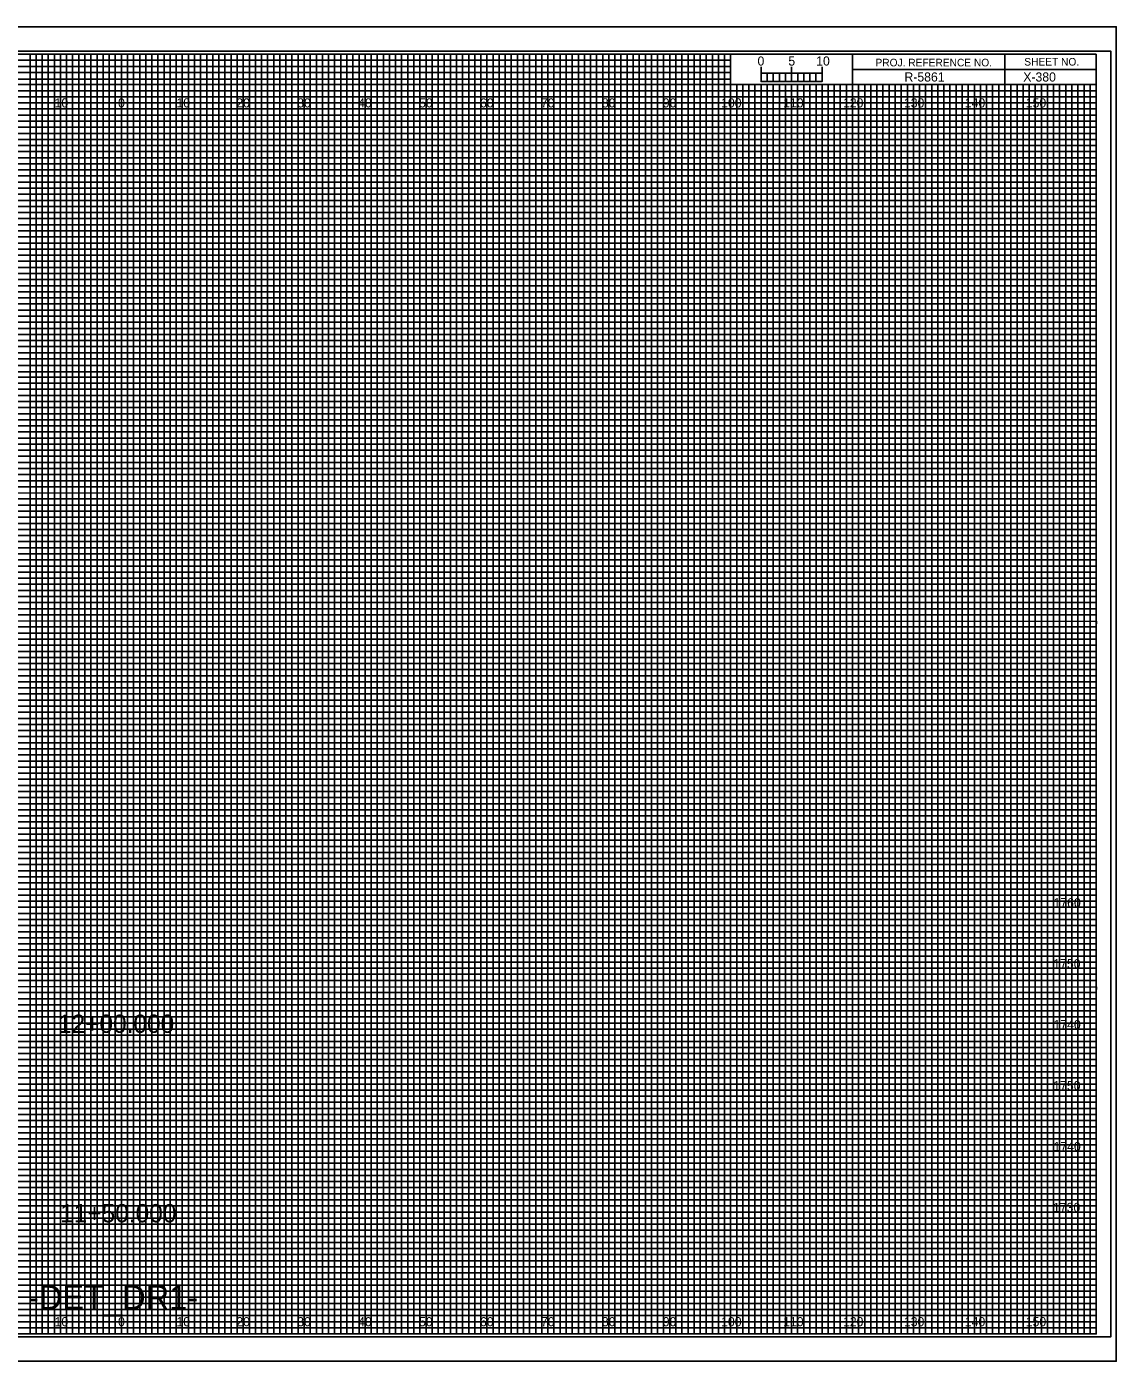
# Model space of a CAD drawing. Extents: x -13 to 323, y -5 to 434.
# Drawn here: x 144.5 to 323.3, y 215.5 to 434.5 of the extents above; entities that cross this region are included whole.
import ezdxf

# ---------------------------------------------------------------- set-up
doc = ezdxf.new("R2010")
doc.units = 0
for name, color, linetype in [('Prop Horizontal Alignment', 7, 'Continuous'), ('Prop XS Alignment Label', 7, 'Continuous'), ('Prop XS Bar Scale Labels', 7, 'Continuous'), ('Prop XS Project Number', 7, 'Continuous'), ('Prop XS Sheet Number', 7, 'Continuous'), ('Raster_Level_0', 7, 'Continuous'), ('Scratch_Level_3', 7, 'Continuous'), ('Sheet Cross Section CELL', 7, 'Continuous'), ('Sheet Cross Section Grid Major CELL', 7, 'Continuous'), ('Sheet Cross Section Grid Middle CELL', 7, 'Continuous'), ('Sheet Cross Section Grid Minor 1 CELL', 7, 'Continuous'), ('Sheet Cross Section Grid Minor 2 CELL', 7, 'Continuous'), ('Sheet Cross Section Scale CELL', 7, 'Continuous'), ('Sheet Cutting Line CELL', 7, 'Continuous'), ('Sheet DOT Grid CELL', 7, 'Continuous'), ('Sheet Plot Border Inside CELL', 7, 'Continuous'), ('Sheet Plot Border Outside CELL', 7, 'Continuous')]:
    doc.layers.add(name, color=color, linetype=linetype)

msp = doc.modelspace()

# ---------------------------------------------------------------- linework, layer by layer
at = {"layer": 'Sheet Cross Section CELL'}
for p, q in [((305, 430), (305, 425)), ((305, 425), (305, 430)), ((280, 427.5), (280, 425)), ((320, 427.49), (280, 427.49)), ((280, 425), (320, 425))]:
    msp.add_line(p, q, dxfattribs=at)
for points in [[(320, 430), (0, 430), (0, 220), (320, 220)], [(280, 430), (260, 430), (260, 425.03), (280, 425.03)], [(320, 430), (280, 430), (280, 425), (320, 425)]]:
    msp.add_lwpolyline(points, close=True, dxfattribs=at)
at = {"layer": 'Sheet Cross Section Grid Major CELL'}
for p, q in [((150, 430), (140, 430)), ((150, 220), (150, 430)), ((170, 430), (160, 430)), ((160, 430), (160, 220)), ((170, 220), (170, 430)), ((190, 430), (180, 430)), ((180, 430), (180, 220)), ((190, 220), (190, 430)), ((210, 430), (200, 430)), ((200, 430), (200, 220)), ((210, 220), (210, 430)), ((230, 430), (220, 430)), ((220, 430), (220, 220)), ((230, 220), (230, 430)), ((250, 430), (240, 430)), ((240, 430), (240, 220)), ((250, 220), (250, 430)), ((260, 430), (260, 220)), ((270, 220), (270, 425)), ((290, 425), (280, 425)), ((280, 425), (280, 220)), ((290, 220), (290, 425)), ((310, 425), (300, 425)), ((300, 425), (300, 220)), ((310, 220), (310, 425)), ((160, 220), (150, 220)), ((180, 220), (170, 220)), ((200, 220), (190, 220)), ((220, 220), (210, 220)), ((240, 220), (230, 220)), ((260, 220), (250, 220)), ((280, 220), (270, 220)), ((300, 220), (290, 220)), ((320, 220), (310, 220)), ((320, 220), (320, 220))]:
    msp.add_line(p, q, dxfattribs=at)
for points in [[(0, 420), (320, 420), (320, 410), (0, 410)], [(0, 400), (320, 400), (320, 390), (0, 390)], [(0, 380), (320, 380), (320, 370), (0, 370)], [(0, 360), (320, 360), (320, 350), (0, 350)], [(0, 340), (320, 340), (320, 330), (0, 330)], [(0, 320), (320, 320), (320, 310), (0, 310)], [(0, 300), (320, 300), (320, 290), (0, 290)], [(0, 280), (320, 280), (320, 270), (0, 270)], [(0, 260), (320, 260), (320, 250), (0, 250)], [(0, 240), (320, 240), (320, 230), (0, 230)]]:
    msp.add_lwpolyline(points, dxfattribs=at)
at = {"layer": 'Sheet Cross Section Grid Middle CELL'}
for points in [[(135, 430), (145, 430), (145, 220), (155, 220), (155, 430), (165, 430), (165, 220), (175, 220), (175, 430), (185, 430), (185, 220), (195, 220), (195, 430), (205, 430), (205, 220), (215, 220), (215, 430), (225, 430), (225, 220), (235, 220), (235, 430), (245, 430), (245, 220), (255, 220), (255, 430), (259.93, 430), (260, 430), (260, 425), (264.99, 425), (264.99, 220), (275, 220), (275, 425), (285, 425), (285, 220), (295, 220), (295, 425), (305, 425), (305, 220), (315, 220), (315, 425)], [(0, 425), (275, 425)], [(0, 405), (320, 405), (320, 415), (0, 415)], [(0, 385), (320, 385), (320, 395), (0, 395)], [(0, 365), (320, 365), (320, 375), (0, 375)], [(0, 345), (320, 345), (320, 355), (0, 355)], [(0, 325), (320, 325), (320, 335), (0, 335)], [(0, 305), (320, 305), (320, 315), (0, 315)], [(0, 285), (320, 285), (320, 295), (0, 295)], [(0, 265), (320, 265), (320, 275), (0, 275)], [(0, 245), (320, 245), (320, 255), (0, 255)], [(0, 225), (320, 225), (320, 235), (0, 235)]]:
    msp.add_lwpolyline(points, dxfattribs=at)
at = {"layer": 'Sheet Cross Section Grid Minor 1 CELL'}
for p, q in [((0, 429), (260, 429)), ((260, 427.98), (0, 427.98)), ((260, 429), (260, 427.98)), ((0, 427), (260, 427)), ((260, 425.89), (0, 425.89)), ((260, 427), (260, 425.89)), ((0, 424), (320, 424))]:
    msp.add_line(p, q, dxfattribs=at)
for points in [[(0, 423), (270, 423), (320, 423), (320, 422), (0, 422)], [(0, 421), (320, 421), (320, 419), (0, 419)], [(0, 418), (320, 418), (320, 417), (0, 416.98)], [(0, 416), (320, 416), (320, 414), (0, 414)], [(0, 413), (320, 413), (320, 412), (0, 412)], [(0, 411), (320, 411), (320, 409), (0, 409)], [(0, 408), (320, 408), (320, 407), (0, 407)], [(0, 406), (320, 406), (320, 404), (0, 404)], [(0, 403), (320, 403), (320, 402), (0, 402)], [(0, 401), (320, 401), (320, 399), (0, 399)], [(0, 398), (320, 398), (320, 397), (0, 397)], [(0, 396), (320, 396), (320, 393.95), (320, 393), (320, 392), (0, 392)], [(0, 394), (320, 394), (320, 393), (0, 393)], [(0, 391), (320, 391), (320, 389), (0, 389.03)], [(0, 389.03), (320, 389), (320, 388), (0, 388)], [(0, 387), (320, 387), (320, 386), (0, 386)], [(0, 384), (320, 384), (320, 383), (0, 383)], [(0, 382), (320, 382), (320, 381), (0, 381)], [(-0.07, 378.89), (320, 378.89), (320, 377.88), (-0.07, 377.88)], [(0, 377), (320, 377), (320, 376), (0, 376)], [(0, 374), (320, 374), (320, 373), (0, 373)], [(0, 372), (320, 372), (320, 371), (0, 371)], [(0, 369), (320, 369), (320, 368), (0, 368)], [(0, 367), (320, 367), (320, 366), (0, 366)], [(0, 364), (320, 364), (320, 363), (0, 363)], [(0, 362), (320, 362), (320, 361), (0, 361)], [(0, 359), (320, 359), (319.99, 357.98), (0, 358)], [(0, 357), (320, 357), (320, 356), (0, 356)], [(0, 354), (320, 354), (320, 353), (0, 353)], [(0, 352), (320, 352), (320, 351), (0, 351)], [(0, 349), (320, 349), (320, 348), (0, 348)], [(0, 347), (320, 347), (320, 346), (0, 346)], [(0, 344), (320, 344), (320, 343), (0, 343)], [(0, 342), (320, 342), (320, 341), (0, 341)], [(0, 339), (320, 339), (320, 338), (0, 338)], [(0, 336.99), (320.07, 336.91), (320, 336), (0, 336)], [(0, 334), (320, 334), (320, 333), (0, 333)], [(0, 332), (320, 332), (320, 331), (0, 331)], [(0, 329), (320, 329), (320, 328), (0, 328)], [(0, 327), (320, 327), (320, 326), (0, 326)], [(0, 324), (320, 324), (320, 323), (0, 323)], [(0, 322), (320, 322), (320, 321), (0, 321)], [(0, 319), (320, 319), (320, 318), (0, 318)], [(0, 317), (320, 317), (320, 316), (0, 316)], [(0, 314), (320, 314), (320, 313), (0, 313)], [(0, 312), (320, 312), (320, 311), (0, 311)], [(0, 309), (320, 309), (320, 308), (0, 308)], [(0, 307), (320, 307), (320, 306), (0, 306)], [(0, 304), (320, 304), (320, 303), (0, 303)], [(0, 302), (320, 302), (320, 301), (0, 301)], [(0, 299), (320, 299), (319.99, 297.98), (0, 298)], [(0, 297), (320, 297), (320, 296), (0, 296)], [(0, 294), (320, 294), (320, 293), (0, 293)], [(0, 292), (320, 292), (320, 291), (0, 291)], [(0, 289), (320, 289), (320, 288), (0, 288)], [(0, 287), (320, 287), (320, 286), (0, 286)], [(0, 284), (320, 284), (320, 283), (0, 283)], [(0, 282), (320, 282), (320, 281), (0, 281)], [(0, 279), (320, 279), (320, 278), (0, 278)], [(0, 276.99), (320.07, 276.91), (320, 276), (0, 276)], [(0, 274), (320, 274), (320, 273), (0, 273)], [(0, 272), (320, 272), (320, 271), (0, 271)], [(0, 269), (320, 269), (320, 268), (0, 268)], [(0, 267), (320, 267), (320, 266), (0, 266)], [(0, 264), (320, 264), (320, 263), (0, 263)], [(0, 262), (320, 262), (320, 261), (0, 261)], [(0, 259), (320, 259), (320, 258), (0, 258)], [(0, 257), (320, 257), (320, 256), (0, 256)], [(0, 254), (320, 254), (320, 253), (0, 253)], [(0, 252), (320, 252), (320, 251), (0, 251)], [(0, 249), (320, 249), (320, 248), (0, 248)], [(0, 247), (320, 247), (320, 246), (0, 246)], [(0, 244), (320, 244), (320, 243), (0, 243)], [(0, 242), (320, 242), (320, 241), (0, 241)], [(0, 239), (320, 239), (320, 238), (0, 238)], [(0, 237), (320, 237), (320, 236), (0, 236)], [(0, 234), (320, 234), (320, 233), (0, 233)], [(0, 232), (320, 232), (320, 231), (0, 231)], [(0, 229), (320, 229), (320, 228), (0, 228)], [(0, 227), (320, 227), (320, 226), (0, 226)], [(0, 224), (320, 224), (320, 223), (0, 223)], [(0, 222), (320, 222), (320, 221), (0, 221)]]:
    msp.add_lwpolyline(points, dxfattribs=at)
at = {"layer": 'Sheet Cross Section Grid Minor 2 CELL'}
for p, q in [((267, 425), (266.01, 425)), ((266.01, 425), (266.01, 220)), ((267, 220), (267, 425)), ((269, 425), (268, 425)), ((268, 425), (268, 220)), ((269, 220), (269, 425)), ((266.01, 220), (265, 220)), ((268, 220), (267, 220))]:
    msp.add_line(p, q, dxfattribs=at)
for points in [[(145, 220), (146, 220), (146, 430), (147, 430), (147, 220)], [(147, 220), (148, 220), (148, 430), (149, 430), (149, 220)], [(150, 220), (151, 220), (151, 430), (152, 430), (152, 220)], [(152, 220), (153, 220), (153, 430), (154, 430), (154, 220)], [(155, 220), (156, 220), (156, 430), (157, 430), (157, 220)], [(157, 220), (158, 220), (158, 430), (159, 430), (159, 220)], [(160, 220), (161, 220), (161, 430), (162, 430), (162, 220)], [(162, 220), (163, 220), (163, 430), (164, 430), (164, 220)], [(165, 220), (166, 220), (166, 430), (167, 430), (167, 220)], [(167, 220), (168, 220), (168, 430), (169, 430), (169, 220)], [(170, 220), (171, 220), (171, 430), (172, 430), (172, 220)], [(172, 220), (173, 220), (173, 430), (174, 430), (174, 220)], [(175, 220), (176, 220), (176, 430), (177, 430), (177, 220)], [(177, 220), (178, 220), (178, 430), (179, 430), (179, 220)], [(180, 220), (181, 220), (181, 430), (182, 430), (182, 220)], [(182, 220), (183, 220), (183, 430), (184, 430), (184, 220)], [(185, 220), (186, 220), (186, 430), (187, 430), (187, 220)], [(187, 220), (188, 220), (188, 430), (189, 430), (189, 220)], [(190, 220), (191, 220), (191, 430), (192, 430), (192, 220)], [(192, 220), (193, 220), (193, 430), (194, 430), (194, 220)], [(195, 220), (196, 220), (196, 430), (197, 430), (197, 220)], [(197, 220), (198, 220), (198, 430), (199, 430), (199, 220)], [(200, 220), (201, 220), (201, 430), (202, 430), (202, 220)], [(202, 220), (203, 220), (203, 430), (204, 430), (204, 220)], [(205, 220), (206, 220), (206, 430), (207, 430), (207, 220)], [(207, 220), (208, 220), (208, 430), (209, 430), (209, 220)], [(210, 220), (211, 220), (211, 430), (212, 430), (212, 220)], [(212, 220), (213, 220), (213, 430), (214, 430), (214, 220)], [(215, 220), (216, 220), (216, 430), (217, 430), (217, 220)], [(217, 220), (218, 220), (218, 430), (219, 430), (219, 220)], [(220, 220), (221, 220), (221, 430), (222, 430), (222, 220)], [(222, 220), (223, 220), (223, 430), (224, 430), (224, 220)], [(225, 220), (226, 220), (226, 430), (227, 430), (227, 220)], [(227, 220), (228, 220), (228, 430), (229, 430), (229, 220)], [(230, 220), (231, 220), (231, 430), (232, 430), (232, 220)], [(232, 220), (233, 220), (233, 430), (234, 430), (234, 220)], [(235, 220), (236, 220), (236, 430), (237, 430), (237, 220)], [(237, 220), (238, 220), (238, 430), (239, 430), (239, 220)], [(240, 220), (241, 220), (241, 430), (242, 430), (242, 220)], [(242, 220), (243, 220), (243, 430), (244, 430), (244, 220)], [(245, 220), (246, 220), (246, 430), (247, 430), (247, 220)], [(247, 220), (248, 220), (248, 430), (249, 430), (249, 220)], [(250, 220), (251, 220), (251, 430), (252, 430), (252, 220)], [(252, 220), (253, 220), (253, 430), (254, 430), (254, 220)], [(255, 220), (256, 220), (256, 430), (257, 430), (257, 220)], [(257, 220), (258, 220), (258, 430), (259, 430), (259, 220)], [(260, 220), (261, 220), (261, 425), (262.02, 425), (262.02, 220)], [(262, 220), (263, 220), (263, 425), (263.99, 425), (263.99, 220)], [(270, 220), (270.98, 220), (270.98, 425), (272, 425), (272, 220)], [(272, 220), (273, 220), (273, 425), (274.05, 425), (274.05, 220)], [(275, 220), (276, 220), (276, 425), (277, 425), (277, 220)], [(277, 220), (278, 220), (278, 425), (279, 425), (279, 220)], [(280, 220), (281, 220), (281, 425), (282, 425), (282, 220)], [(282, 220), (283, 220), (283, 425), (284, 425), (284, 220)], [(285, 220), (286, 220), (286, 425), (287, 425), (287, 220)], [(287, 220), (288, 220), (288, 425), (289, 425), (289, 220)], [(290, 220), (291, 220), (291, 425), (292, 425), (292, 220)], [(292, 220), (293, 220), (293, 425), (294, 425), (294, 220)], [(295, 220), (296, 220), (296, 425), (297, 425), (297, 220)], [(297, 220), (298, 220), (298, 425), (299, 425), (299, 220)], [(300, 220), (301, 220), (301, 425), (302, 425), (302, 220)], [(302, 220), (303, 220), (303, 425), (304, 425), (304, 220)], [(305, 220), (306, 220), (306, 425), (307, 425), (307, 220)], [(307, 220), (308, 220), (308, 425), (309, 425), (309, 220)], [(310, 220), (311, 220), (311, 425), (312, 425), (312, 220)], [(312, 220), (313, 220), (313, 425), (314, 425), (314, 220)], [(315, 220), (316, 220), (316, 425), (317, 425), (317, 220)], [(317, 220), (318, 220), (318, 425), (319, 425), (319, 220)]]:
    msp.add_lwpolyline(points, dxfattribs=at)
at = {"layer": 'Sheet Cross Section Scale CELL'}
for p, q in [((265, 425.49), (265, 427.9)), ((265, 426.9), (265, 427.9)), ((270, 425.49), (270, 427.9)), ((275, 425.49), (275, 427.9)), ((275, 426.9), (275, 427.9))]:
    msp.add_line(p, q, dxfattribs=at)
for points in [[(275, 426.9), (265, 426.9), (265, 425.49), (275, 425.49)], [(265, 426.9), (266, 426.9), (266, 425.49), (265, 425.49)], [(267, 426.9), (268, 426.9), (268, 425.49), (267, 425.49)], [(269, 426.9), (270, 426.9), (270, 425.49), (269, 425.49)], [(271, 426.9), (272, 426.9), (272, 425.49), (271, 425.49)], [(273, 426.9), (274, 426.9), (274, 425.49), (273, 425.49)]]:
    msp.add_lwpolyline(points, close=True, dxfattribs=at)
at = {"layer": 'Sheet Cutting Line CELL'}
for p, q in [((323.3, 434.5), (-13.4, 434.5)), ((-13.4, 215.5), (323.3, 215.5))]:
    msp.add_line(p, q, dxfattribs=at)
at = {"layer": 'Sheet DOT Grid CELL'}
for p, q in [((150, 220), (150, 430)), ((160, 220), (160, 430)), ((170, 220), (170, 430)), ((180, 220), (180, 430)), ((190, 220), (190, 430)), ((200, 220), (200, 430)), ((210, 220), (210, 430)), ((220, 220), (220, 430)), ((230, 220), (230, 430)), ((240, 220), (240, 430)), ((250, 220), (250, 430)), ((260, 220), (260, 424.69)), ((270, 220), (270, 424.69)), ((280, 220), (280, 424.69)), ((290, 220), (290, 424.69)), ((300, 220), (300, 424.69)), ((310, 220), (310, 424.69)), ((0, 420), (320, 420)), ((0, 410), (320, 410)), ((0, 400), (320, 400)), ((0, 390), (320, 390)), ((0, 380), (320, 380)), ((0, 370), (320, 370)), ((0, 360), (320, 360)), ((0, 350), (320, 350)), ((0, 340), (320, 340)), ((0, 330), (320, 330)), ((0, 320), (320, 320)), ((0, 310), (320, 310)), ((0, 300), (320, 300)), ((0, 290), (320, 290)), ((0, 280), (320, 280)), ((0, 270), (320, 270)), ((0, 260), (320, 260)), ((0, 250), (320, 250)), ((0, 240), (320, 240)), ((0, 230), (320, 230))]:
    msp.add_line(p, q, dxfattribs=at)
at = {"layer": 'Sheet Plot Border Inside CELL'}
msp.add_lwpolyline([(-10.8, 219.5), (322.4, 219.5), (322.4, 430.5), (-10.8, 430.5)], close=True, dxfattribs=at)
at = {"layer": 'Sheet Plot Border Outside CELL'}
msp.add_lwpolyline([(-13.4, 215.5), (323.3, 215.5), (323.3, 434.5), (-13.4, 434.5)], close=True, dxfattribs=at)

# ---------------------------------------------------------------- texts
at = {"layer": 'Prop Horizontal Alignment'}
for s, p in [('12+00.000', (149.59, 269.39)), ('11+50.000', (149.95, 238.3))]:
    msp.add_text(s, height=3, dxfattribs=at).set_placement(p)
at = {"layer": 'Prop XS Alignment Label'}
msp.add_text('-DET_DR1-', height=4, dxfattribs=at).set_placement((144.67, 224))
at = {"layer": 'Prop XS Bar Scale Labels'}
for s, p in [('5', (269.47, 428.12)), ('10', (274.04, 428.12))]:
    msp.add_text(s, height=1.5, dxfattribs=at).set_placement(p)
at = {"layer": 'Prop XS Project Number'}
msp.add_text('R-5861', height=1.5, dxfattribs=at).set_placement((288.53, 425.5))
at = {"layer": 'Prop XS Sheet Number'}
msp.add_text('X-380', height=1.5, dxfattribs=at).set_placement((308.03, 425.5))
at = {"layer": 'Raster_Level_0'}
for s, p in [('10', (149.04, 421.25)), ('0', (159.45, 421.25)), ('0', (159.45, 421.25)), ('10', (169.04, 421.25)), ('20', (178.86, 421.25)), ('30', (188.86, 421.25)), ('40', (198.86, 421.25)), ('50', (208.86, 421.25)), ('60', (218.86, 421.25)), ('70', (228.86, 421.25)), ('80', (238.86, 421.25)), ('90', (248.86, 421.25)), ('100', (258.44, 421.25)), ('110', (268.62, 421.25)), ('120', (278.44, 421.25)), ('130', (288.44, 421.25)), ('140', (298.44, 421.25)), ('150', (308.44, 421.25)), ('10', (149.04, 221.25)), ('0', (159.45, 221.25)), ('0', (159.45, 221.25)), ('10', (169.04, 221.25)), ('20', (178.86, 221.25)), ('30', (188.86, 221.25)), ('40', (198.86, 221.25)), ('50', (208.86, 221.25)), ('60', (218.86, 221.25)), ('70', (228.86, 221.25)), ('80', (238.86, 221.25)), ('90', (248.86, 221.25)), ('100', (258.44, 221.25)), ('110', (268.62, 221.25)), ('120', (278.44, 221.25)), ('130', (288.44, 221.25)), ('140', (298.44, 221.25)), ('150', (308.44, 221.25))]:
    msp.add_text(s, height=1.5, dxfattribs=at).set_placement(p)
at = {"layer": 'Scratch_Level_3'}
for s, p in [('1760', (313, 290)), ('1750', (312.96, 280)), ('1740', (313, 270)), ('1750', (312.96, 260)), ('1740', (313, 250)), ('1730', (312.92, 240))]:
    msp.add_text(s, height=1.5, dxfattribs=at).set_placement(p)
at = {"layer": 'Sheet Cross Section CELL'}
for s, p in [('PROJ. REFERENCE NO.', (283.77, 427.99)), ('SHEET NO.', (308.19, 428.12))]:
    msp.add_text(s, height=1.25, dxfattribs=at).set_placement(p)
at = {"layer": 'Sheet Cross Section Scale CELL'}
msp.add_text('0', height=1.5, dxfattribs=at).set_placement((264.41, 428.12))

doc.saveas('drawing.dxf')
